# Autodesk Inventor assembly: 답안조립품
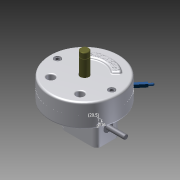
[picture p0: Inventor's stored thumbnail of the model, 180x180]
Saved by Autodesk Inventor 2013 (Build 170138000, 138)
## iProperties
Created: 2015-04
Part Number: 답안조립품
Document SubType Name: Assembly
Designer: Administrator
Author: Administrator
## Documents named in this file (15)
- C:\Documents and Settings\Administrator\바탕 화면\350405V1015\답안조립품.iam
- C:\Documents and Settings\Administrator\바탕 화면\350405V1015\본체.ipt
- C:\Documents and Settings\Administrator\바탕 화면\350405V1015\커버.ipt
- C:\Documents and Settings\Administrator\바탕 화면\350405V1015\커버2.ipt
- C:\Documents and Settings\Administrator\바탕 화면\350405V1015\베어링62_22.ipt
- C:\Documents and Settings\Administrator\바탕 화면\350405V1015\부시.ipt
- C:\Documents and Settings\Administrator\바탕 화면\350405V1015\축.ipt
- C:\Documents and Settings\Administrator\바탕 화면\350405V1015\멈춤링.ipt
- C:\Documents and Settings\Administrator\바탕 화면\350405V1015\슬라이더3.ipt
- C:\Documents and Settings\Administrator\바탕 화면\350405V1015\슬라이더.ipt
- C:\Documents and Settings\Administrator\바탕 화면\350405V1015\슬라이더2.ipt
- C:\Documents and Settings\Administrator\바탕 화면\350405V1015\평행핀.ipt
- C:\Documents and Settings\Administrator\바탕 화면\350405V1015\8-가변스프링.ipt
- C:\Documents and Settings\Administrator\바탕 화면\350405V1015\M 10 x 35.ipt
- C:\Documents and Settings\Administrator\바탕 화면\350405V1015\M 5 x 12.ipt
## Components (6 placed, 4 different names)
1. KS B 1320 B B 5 x  20:1
2. 8-가변스프링:1
3. M 10 x 35:1
4. M 10 x 35:2
5. M 5 x 12:1
6. M 5 x 12:2
